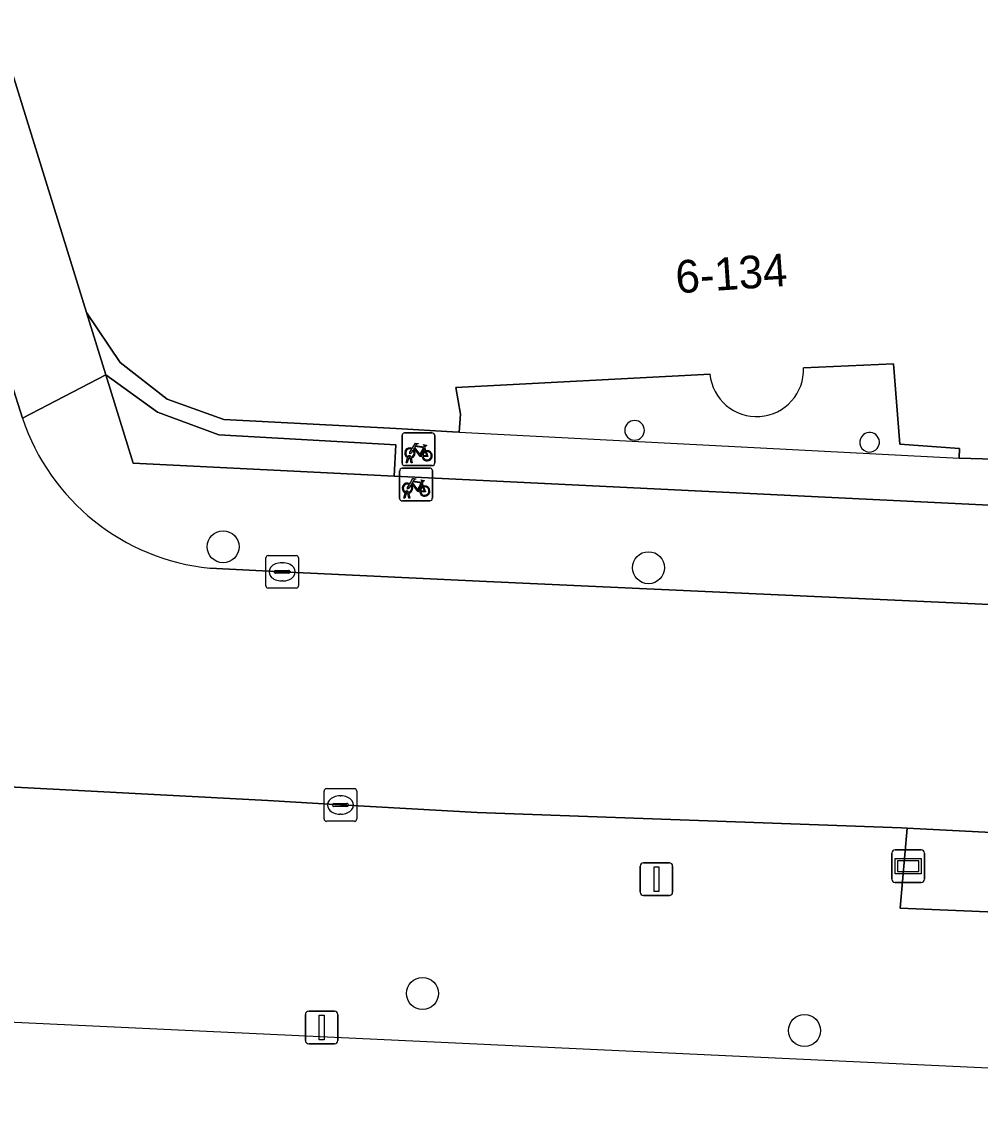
# Model space of a CAD drawing. Extents: x 161248 to 161848, y 384871 to 385383.
# Drawn here: x 161461.02 to 161490.34, y 384880.89 to 384914.33 of the extents above; entities that cross this region are included whole.
import ezdxf

# ---------------------------------------------------------------- set-up
doc = ezdxf.new("R2010")
doc.units = 0
for name, color, linetype in [('IMGEO_Berm_groen', 7, 'Continuous'), ('IMGEO_Boom', 7, 'Continuous'), ('IMGEO_Erf', 7, 'Continuous'), ('IMGEO_Fietsenrek', 7, 'Continuous'), ('IMGEO_Grasland_overig', 7, 'Continuous'), ('IMGEO_Groenvoorziening', 7, 'Continuous'), ('IMGEO_Haag', 7, 'Continuous'), ('IMGEO_Kolk', 7, 'Continuous'), ('IMGEO_Lichtmast', 7, 'Continuous'), ('IMGEO_Pand', 7, 'Continuous'), ('IMGEO_Pand_nummerreeks', 7, 'Continuous'), ('IMGEO_Pand_overbouw', 7, 'Continuous'), ('IMGEO_Rijbaan_lokaal_open', 7, 'Continuous'), ('IMGEO_Voetpad_open', 7, 'Continuous'), ('IMGEO_Wegwijzer', 7, 'Continuous')]:
    doc.layers.add(name, color=color, linetype=linetype)

msp = doc.modelspace()

# ---------------------------------------------------------------- linework, layer by layer
at = {"layer": 'IMGEO_Berm_groen'}
for points in [[(161594.701, 384882.499), (161594.709, 384882.686), (161587.754, 384882.945), (161578.585, 384883.414), (161564.755, 384883.961), (161553.631, 384884.443), (161549.641, 384884.61), (161543.014, 384884.888), (161528.41, 384885.51), (161516.282, 384885.98), (161504.167, 384886.488), (161500, 384886.678), (161491.061, 384887.085), (161487.893, 384887.217), (161488.111, 384889.666), (161487.937, 384889.675), (161474.955, 384890.148), (161470.772, 384890.376), (161468.545, 384890.508), (161452.703, 384891.345), (161438.246, 384892.076), (161437.485, 384892.094)], [(161417.572, 384886.526), (161433.198, 384885.047), (161433.661, 384885.003), (161462.543, 384883.65), (161521.484, 384880.889)]]:
    msp.add_lwpolyline(points, dxfattribs=at)
at = {"layer": 'IMGEO_Boom'}
for centre in [(161467.18, 384898.275), (161480.198, 384897.634), (161473.282, 384884.612), (161484.971, 384883.476)]:
    msp.add_circle(centre, 0.489, dxfattribs=at)
at = {"layer": 'IMGEO_Erf'}
for points in [[(161482.079, 384903.557), (161474.306, 384903.145), (161474.445, 384902.333), (161474.4, 384901.782), (161474.197, 384901.793), (161472.472, 384901.888), (161467.205, 384902.169), (161465.471, 384902.789), (161464.028, 384903.912), (161462.997, 384905.435), (161463.597, 384903.538), (161465.178, 384902.396), (161467.049, 384901.693), (161472.464, 384901.396), (161472.417, 384900.431), (161492.094, 384899.477), (161500, 384899.077), (161511.33, 384898.504), (161531.851, 384897.478), (161531.908, 384898.429), (161531.936, 384898.905), (161500, 384900.507)], [(161500, 384900.507), (161492.153, 384900.901), (161491.494, 384900.934), (161489.698, 384900.984), (161489.713, 384901.276), (161487.889, 384901.412), (161487.689, 384903.87), (161484.941, 384903.75)]]:
    msp.add_lwpolyline(points, dxfattribs=at)
for centre, radius, start, end in [((161483.507, 384903.692), 1.435, 185.3791, 2.3367), ((161479.771, 384901.835), 0.3, 90, 270), ((161479.771, 384901.835), 0.3, 270, 90), ((161486.962, 384901.471), 0.3, 128.5585, 309.6571), ((161486.962, 384901.471), 0.3, 309.5127, 128.7029)]:
    msp.add_arc(centre, radius, start, end, dxfattribs=at)
at = {"layer": 'IMGEO_Fietsenrek'}
for p, q in [((161472.656, 384900.832), (161472.656, 384901.673)), ((161472.656, 384901.673), (161472.656, 384900.832)), ((161472.731, 384901.757), (161473.572, 384901.757)), ((161473.572, 384901.757), (161472.731, 384901.757)), ((161473.656, 384901.682), (161473.656, 384900.841)), ((161473.656, 384900.841), (161473.656, 384901.682)), ((161473.343, 384901.306), (161473.379, 384901.211)), ((161472.783, 384900.841), (161472.822, 384901.001)), ((161472.817, 384900.841), (161472.783, 384900.841)), ((161472.852, 384900.989), (161472.817, 384900.841)), ((161472.894, 384901.013), (161472.893, 384901.017)), ((161472.935, 384900.841), (161472.901, 384900.983)), ((161472.925, 384901.024), (161472.926, 384901.017)), ((161472.933, 384900.987), (161472.968, 384900.841)), ((161472.968, 384900.841), (161472.935, 384900.841)), ((161472.583, 384899.753), (161472.583, 384900.594)), ((161472.583, 384900.594), (161472.583, 384899.753)), ((161472.658, 384900.678), (161473.499, 384900.678)), ((161473.499, 384900.678), (161472.658, 384900.678)), ((161473.581, 384900.757), (161472.74, 384900.757)), ((161472.74, 384900.757), (161473.581, 384900.757)), ((161473.583, 384900.603), (161473.583, 384899.762)), ((161473.583, 384899.762), (161473.583, 384900.603)), ((161473.27, 384900.227), (161473.306, 384900.132)), ((161472.71, 384899.762), (161472.749, 384899.922)), ((161472.779, 384899.91), (161472.744, 384899.762)), ((161472.821, 384899.934), (161472.82, 384899.938)), ((161472.862, 384899.762), (161472.828, 384899.904)), ((161472.852, 384899.945), (161472.853, 384899.938)), ((161472.86, 384899.908), (161472.895, 384899.762)), ((161473.508, 384899.678), (161472.667, 384899.678)), ((161472.667, 384899.678), (161473.508, 384899.678)), ((161472.744, 384899.762), (161472.71, 384899.762)), ((161472.895, 384899.762), (161472.862, 384899.762))]:
    msp.add_line(p, q, dxfattribs=at)
for points in [[(161472.99, 384901.231), (161472.938, 384901.141), (161472.898, 384901.116), (161472.899, 384901.163), (161472.954, 384901.257)], [(161472.969, 384901.283), (161473.064, 384901.447), (161473.15, 384901.433), (161473.152, 384901.424), (161473.096, 384901.413), (161473.069, 384901.368), (161473.325, 384901.327)], [(161473.265, 384901.039), (161473.215, 384901.039), (161473.024, 384901.29), (161473.005, 384901.258)], [(161473.312, 384901.302), (161473.055, 384901.343), (161473.038, 384901.314), (161473.205, 384901.094), (161473.312, 384901.302)], [(161473.36, 384901.204), (161473.33, 384901.281), (161473.221, 384901.063), (161473.264, 384901.063)], [(161473.294, 384901.063), (161473.414, 384901.062), (161473.37, 384901.176)], [(161473.39, 384901.183), (161473.445, 384901.038), (161473.295, 384901.038)], [(161473.325, 384901.327), (161473.35, 384901.376), (161473.344, 384901.38), (161473.321, 384901.384), (161473.309, 384901.391), (161473.308, 384901.394), (161473.31, 384901.399), (161473.405, 384901.384), (161473.407, 384901.374), (161473.397, 384901.361), (161473.385, 384901.355), (161473.371, 384901.361), (161473.343, 384901.306)], [(161472.917, 384900.152), (161472.865, 384900.062), (161472.825, 384900.037), (161472.826, 384900.084), (161472.881, 384900.178)], [(161472.896, 384900.204), (161472.991, 384900.368), (161473.077, 384900.354), (161473.079, 384900.345), (161473.023, 384900.334), (161472.996, 384900.289), (161473.252, 384900.248)], [(161473.192, 384899.96), (161473.142, 384899.96), (161472.951, 384900.211), (161472.932, 384900.179)], [(161473.239, 384900.223), (161472.982, 384900.264), (161472.965, 384900.235), (161473.132, 384900.015), (161473.239, 384900.223)], [(161473.287, 384900.125), (161473.257, 384900.202), (161473.148, 384899.984), (161473.191, 384899.984)], [(161473.252, 384900.248), (161473.277, 384900.297), (161473.271, 384900.301), (161473.248, 384900.305), (161473.236, 384900.312), (161473.235, 384900.315), (161473.237, 384900.32), (161473.332, 384900.305), (161473.334, 384900.295), (161473.324, 384900.282), (161473.312, 384900.276), (161473.298, 384900.282), (161473.27, 384900.227)], [(161473.221, 384899.984), (161473.341, 384899.983), (161473.297, 384900.097)], [(161473.317, 384900.104), (161473.372, 384899.959), (161473.222, 384899.959)]]:
    msp.add_lwpolyline(points, dxfattribs=at)
for centre, radius, start, end in [((161472.734, 384901.679), 0.0779, 92.4484, 184.2845), ((161472.734, 384901.679), 0.0779, 92.4484, 184.2845), ((161473.578, 384901.679), 0.0779, 2.4484, 94.2845), ((161473.578, 384901.679), 0.0779, 2.4484, 94.2845), ((161472.896, 384901.142), 0.159, 62.6766, 242.1369), ((161472.896, 384901.142), 0.129, 63.3192, 238.903), ((161472.896, 384901.142), 0.129, 283.6043, 43.4302), ((161472.896, 384901.142), 0.159, 283.5766, 46.6042), ((161473.423, 384901.058), 0.159, 113.3408, 178.3217), ((161473.423, 384901.058), 0.159, 187.0065, 105.7708), ((161473.423, 384901.058), 0.129, 113.923, 177.9556), ((161473.423, 384901.058), 0.129, 188.6715, 104.5883), ((161472.734, 384900.835), 0.0779, 182.4484, 274.2845), ((161472.734, 384900.835), 0.0779, 182.4484, 274.2845), ((161472.876, 384901.013), 0.0499, 12.8025, 158.6934), ((161472.896, 384901.142), 0.159, 253.9967, 271.7867), ((161472.876, 384901.013), 0.0174, 12.8025, 163.4502), ((161472.896, 384901.142), 0.129, 253.415, 269.0204), ((161473.578, 384900.835), 0.0779, 272.4484, 4.2845), ((161473.578, 384900.835), 0.0779, 272.4484, 4.2845), ((161472.661, 384900.6), 0.0779, 92.4484, 184.2845), ((161472.661, 384900.6), 0.0779, 92.4484, 184.2845), ((161473.505, 384900.6), 0.0779, 2.4484, 94.2845), ((161473.505, 384900.6), 0.0779, 2.4484, 94.2845), ((161472.823, 384900.063), 0.159, 62.6766, 242.1369), ((161472.823, 384900.063), 0.129, 63.3192, 238.903), ((161472.823, 384900.063), 0.129, 283.6043, 43.4302), ((161472.823, 384900.063), 0.159, 283.5766, 46.6042), ((161472.803, 384899.934), 0.0499, 12.8025, 158.6934), ((161472.823, 384900.063), 0.159, 253.9967, 271.7867), ((161472.803, 384899.934), 0.0174, 12.8025, 163.4502), ((161472.823, 384900.063), 0.129, 253.415, 269.0204), ((161473.35, 384899.979), 0.159, 113.3408, 178.3217), ((161473.35, 384899.979), 0.159, 187.0065, 105.7708), ((161473.35, 384899.979), 0.129, 113.923, 177.9556), ((161473.35, 384899.979), 0.129, 188.6715, 104.5883), ((161472.661, 384899.756), 0.0779, 182.4484, 274.2845), ((161472.661, 384899.756), 0.0779, 182.4484, 274.2845), ((161473.505, 384899.756), 0.0779, 272.4484, 4.2845), ((161473.505, 384899.756), 0.0779, 272.4484, 4.2845)]:
    msp.add_arc(centre, radius, start, end, dxfattribs=at)
at = {"layer": 'IMGEO_Grasland_overig'}
msp.add_lwpolyline([(161464.426, 384900.827), (161472.417, 384900.431), (161472.464, 384901.396), (161467.049, 384901.693), (161465.178, 384902.396), (161463.597, 384903.538)], close=True, dxfattribs=at)
at = {"layer": 'IMGEO_Groenvoorziening'}
msp.add_lwpolyline([(161497.843, 384889.167), (161488.111, 384889.666), (161487.893, 384887.217), (161491.061, 384887.085)], dxfattribs=at)
at = {"layer": 'IMGEO_Haag'}
msp.add_lwpolyline([(161472.464, 384901.396), (161467.049, 384901.693), (161465.178, 384902.396), (161463.597, 384903.538), (161464.426, 384900.827), (161472.417, 384900.431)], close=True, dxfattribs=at)
msp.add_lwpolyline([(161497.843, 384889.167), (161488.111, 384889.666), (161487.893, 384887.217), (161491.061, 384887.085)], dxfattribs=at)
at = {"layer": 'IMGEO_Kolk'}
for p, q in [((161468.487, 384897.081), (161468.487, 384897.933)), ((161468.562, 384898.007), (161469.414, 384898.007)), ((161469.488, 384897.933), (161469.488, 384897.081)), ((161468.746, 384897.501), (161468.746, 384897.513)), ((161468.789, 384897.55), (161469.187, 384897.55)), ((161468.975, 384897.787), (161469, 384897.787)), ((161469.23, 384897.513), (161469.23, 384897.501)), ((161469.184, 384897.464), (161468.786, 384897.464)), ((161468.998, 384897.227), (161468.973, 384897.227)), ((161469.414, 384897.007), (161468.562, 384897.007)), ((161470.271, 384889.95), (161470.271, 384890.802)), ((161470.346, 384890.876), (161471.198, 384890.876)), ((161471.272, 384890.802), (161471.272, 384889.95)), ((161470.759, 384890.656), (161470.784, 384890.656)), ((161470.53, 384890.37), (161470.53, 384890.382)), ((161470.968, 384890.333), (161470.57, 384890.333)), ((161470.573, 384890.419), (161470.971, 384890.419)), ((161471.014, 384890.382), (161471.014, 384890.37)), ((161471.198, 384889.876), (161470.346, 384889.876)), ((161470.782, 384890.096), (161470.757, 384890.096))]:
    msp.add_line(p, q, dxfattribs=at)
for points in [[(161468.487, 384897.081), (161468.487, 384897.933)], [(161468.562, 384898.007), (161469.414, 384898.007)], [(161469.488, 384897.933), (161469.488, 384897.081)], [(161469.414, 384897.007), (161468.562, 384897.007)], [(161470.271, 384889.95), (161470.271, 384890.802)], [(161470.346, 384890.876), (161471.198, 384890.876)], [(161471.272, 384890.802), (161471.272, 384889.95)], [(161471.198, 384889.876), (161470.346, 384889.876)]]:
    msp.add_lwpolyline(points, dxfattribs=at)
for centre, radius, start, end in [((161468.564, 384897.931), 0.0765, 91.552, 178.448), ((161468.564, 384897.931), 0.0765, 91.552, 178.448), ((161469.412, 384897.931), 0.0765, 1.552, 88.448), ((161469.412, 384897.931), 0.0765, 1.552, 88.448), ((161468.786, 384897.51), 0.0403, 85.8775, 175.7526), ((161468.783, 384897.5), 0.0366, 178.938, 274.7102), ((161469.187, 384897.507), 0.043, 264.8664, 352.4533), ((161469.191, 384897.512), 0.0386, 1.7309, 96.639), ((161468.564, 384897.083), 0.0765, 181.552, 268.448), ((161468.564, 384897.083), 0.0765, 181.552, 268.448), ((161469.412, 384897.083), 0.0765, 271.552, 358.448), ((161469.412, 384897.083), 0.0765, 271.552, 358.448), ((161470.348, 384890.8), 0.0765, 91.552, 178.448), ((161470.348, 384890.8), 0.0765, 91.552, 178.448), ((161471.196, 384890.8), 0.0765, 1.552, 88.448), ((161471.196, 384890.8), 0.0765, 1.552, 88.448), ((161470.57, 384890.379), 0.0403, 85.8775, 175.7526), ((161470.567, 384890.369), 0.0366, 178.938, 274.7102), ((161470.971, 384890.376), 0.043, 264.8664, 352.4533), ((161470.975, 384890.381), 0.0386, 1.7309, 96.639), ((161470.348, 384889.952), 0.0765, 181.552, 268.448), ((161470.348, 384889.952), 0.0765, 181.552, 268.448), ((161471.196, 384889.952), 0.0765, 271.552, 358.448), ((161471.196, 384889.952), 0.0765, 271.552, 358.448)]:
    msp.add_arc(centre, radius, start, end, dxfattribs=at)
for centre, major_axis, ratio, start_param, end_param in [((161468.974, 384897.507), (-0.387, 0.002), 0.722429, 4.712389, 7.853982), ((161468.999, 384897.507), (-0.39, 0.002), 0.717154, 1.570796, 4.712389), ((161470.758, 384890.376), (-0.387, 0.002), 0.722429, 4.712389, 7.853982), ((161470.783, 384890.376), (-0.39, 0.002), 0.717154, 1.570796, 4.712389)]:
    msp.add_ellipse(centre, major_axis=major_axis, ratio=ratio, start_param=start_param, end_param=end_param, dxfattribs=at)
at = {"layer": 'IMGEO_Lichtmast'}
for p, q in [((161479.946, 384887.706), (161479.946, 384888.506)), ((161479.946, 384888.506), (161479.946, 384887.706)), ((161480.046, 384888.606), (161480.836, 384888.606)), ((161480.836, 384888.606), (161480.046, 384888.606)), ((161480.936, 384888.506), (161480.936, 384887.706)), ((161480.936, 384887.706), (161480.936, 384888.506)), ((161480.836, 384887.606), (161480.046, 384887.606)), ((161480.046, 384887.606), (161480.836, 384887.606)), ((161469.699, 384883.17), (161469.699, 384883.97)), ((161469.699, 384883.97), (161469.699, 384883.17)), ((161469.799, 384884.07), (161470.589, 384884.07)), ((161470.589, 384884.07), (161469.799, 384884.07)), ((161470.689, 384883.97), (161470.689, 384883.17)), ((161470.689, 384883.17), (161470.689, 384883.97)), ((161470.589, 384883.07), (161469.799, 384883.07)), ((161469.799, 384883.07), (161470.589, 384883.07))]:
    msp.add_line(p, q, dxfattribs=at)
for points in [[(161480.366, 384888.481), (161480.516, 384888.481), (161480.516, 384887.731), (161480.366, 384887.731), (161480.366, 384888.481)], [(161470.119, 384883.945), (161470.269, 384883.945), (161470.269, 384883.195), (161470.119, 384883.195), (161470.119, 384883.945)]]:
    msp.add_lwpolyline(points, dxfattribs=at)
for centre, start, end in [((161480.046, 384888.506), 90, 180), ((161480.046, 384888.506), 90, 180), ((161480.836, 384888.506), 0, 90), ((161480.836, 384888.506), 360, 90), ((161480.046, 384887.706), 180, 270), ((161480.046, 384887.706), 180, 270), ((161480.836, 384887.706), 270, 0), ((161480.836, 384887.706), 270, 0), ((161469.799, 384883.97), 90, 180), ((161469.799, 384883.97), 90, 180), ((161470.589, 384883.97), 0, 90), ((161470.589, 384883.97), 360, 90), ((161469.799, 384883.17), 180, 270), ((161469.799, 384883.17), 180, 270), ((161470.589, 384883.17), 270, 0), ((161470.589, 384883.17), 270, 0)]:
    msp.add_arc(centre, 0.1, start, end, dxfattribs=at)
at = {"layer": 'IMGEO_Pand'}
for points in [[(161500, 384915.713), (161473.166, 384917.063), (161470.469, 384917.199), (161465.842, 384917.432), (161465.803, 384917.137), (161460.304, 384915.459), (161459.563, 384917.873), (161459.445, 384917.85), (161459.171, 384917.798), (161462.997, 384905.435), (161464.028, 384903.912), (161465.471, 384902.789), (161467.205, 384902.169), (161472.472, 384901.888), (161474.197, 384901.793), (161474.4, 384901.782), (161474.445, 384902.333), (161474.306, 384903.145), (161482.079, 384903.557)], [(161484.941, 384903.75), (161487.689, 384903.87), (161487.889, 384901.412), (161489.713, 384901.276), (161489.698, 384900.984), (161491.494, 384900.934)]]:
    msp.add_lwpolyline(points, dxfattribs=at)
for centre, radius, start, end in [((161483.507, 384903.692), 1.435, 185.3791, 2.3367), ((161479.771, 384901.835), 0.3, 90, 270), ((161479.771, 384901.835), 0.3, 270, 90), ((161486.962, 384901.471), 0.3, 128.5585, 309.6571), ((161486.962, 384901.471), 0.3, 309.5127, 128.7029)]:
    msp.add_arc(centre, radius, start, end, dxfattribs=at)
at = {"layer": 'IMGEO_Pand_overbouw'}
msp.add_lwpolyline([(161482.079, 384903.557), (161474.306, 384903.145), (161474.445, 384902.333), (161474.4, 384901.782), (161489.698, 384900.984), (161489.713, 384901.276), (161487.889, 384901.412), (161487.689, 384903.87), (161484.941, 384903.75)], dxfattribs=at)
msp.add_arc((161483.507, 384903.692), 1.435, 185.3791, 2.3367, dxfattribs=at)
at = {"layer": 'IMGEO_Rijbaan_lokaal_open'}
for points in [[(161461.041, 384902.205), (161460.368, 384904.332), (161452.677, 384905.212)], [(161532.296, 384894.342), (161500, 384896.083), (161475.245, 384897.212), (161468.988, 384897.507), (161466.772, 384897.621)], [(161437.485, 384892.094), (161438.246, 384892.076), (161452.703, 384891.345), (161468.545, 384890.508), (161470.772, 384890.376), (161474.955, 384890.148), (161487.937, 384889.675), (161488.111, 384889.666), (161497.843, 384889.167)]]:
    msp.add_lwpolyline(points, dxfattribs=at)
msp.add_arc((161467.459, 384904.355), 6.769, 198.5195, 264.1707, dxfattribs=at)
at = {"layer": 'IMGEO_Voetpad_open'}
for points in [[(161448.004, 384944.929), (161451.635, 384932.866), (161453.927, 384925.402), (161456.119, 384918.262), (161458.507, 384910.295), (161460.368, 384904.332), (161461.041, 384902.205), (161463.597, 384903.538), (161462.997, 384905.435), (161459.171, 384917.798), (161457.933, 384921.499), (161455.957, 384927.409)], [(161531.851, 384897.478), (161511.33, 384898.504), (161500, 384899.077), (161492.094, 384899.477), (161472.417, 384900.431), (161464.426, 384900.827), (161463.597, 384903.538), (161461.041, 384902.205)], [(161466.772, 384897.621), (161468.988, 384897.507), (161475.245, 384897.212), (161500, 384896.083), (161532.296, 384894.342), (161531.851, 384897.478)]]:
    msp.add_lwpolyline(points, dxfattribs=at)
msp.add_arc((161467.459, 384904.355), 6.769, 198.5195, 264.1707, dxfattribs=at)
at = {"layer": 'IMGEO_Wegwijzer'}
for p, q in [((161487.647, 384888.105), (161487.647, 384888.905)), ((161487.647, 384888.905), (161487.647, 384888.105)), ((161487.747, 384889.005), (161488.537, 384889.005)), ((161488.537, 384889.005), (161487.747, 384889.005)), ((161488.637, 384888.905), (161488.637, 384888.105)), ((161488.637, 384888.105), (161488.637, 384888.905)), ((161488.537, 384888.005), (161487.747, 384888.005)), ((161487.747, 384888.005), (161488.537, 384888.005))]:
    msp.add_line(p, q, dxfattribs=at)
for points in [[(161487.748, 384888.737), (161488.536, 384888.737), (161488.536, 384888.273), (161487.748, 384888.273), (161487.748, 384888.737)], [(161487.813, 384888.672), (161487.813, 384888.338), (161488.471, 384888.338), (161488.471, 384888.672), (161487.813, 384888.672)]]:
    msp.add_lwpolyline(points, dxfattribs=at)
for centre, start, end in [((161487.747, 384888.905), 90, 180), ((161487.747, 384888.905), 90, 180), ((161488.537, 384888.905), 0, 90), ((161488.537, 384888.905), 360, 90), ((161487.747, 384888.105), 180, 270), ((161487.747, 384888.105), 180, 270), ((161488.537, 384888.105), 270, 0), ((161488.537, 384888.105), 270, 0)]:
    msp.add_arc(centre, 0.1, start, end, dxfattribs=at)

# ---------------------------------------------------------------- texts
at = {"layer": 'IMGEO_Pand_nummerreeks'}
msp.add_text('6-134', height=1, rotation=3.8443, dxfattribs=at).set_placement((161481.056, 384906.024))

doc.saveas('drawing.dxf')
